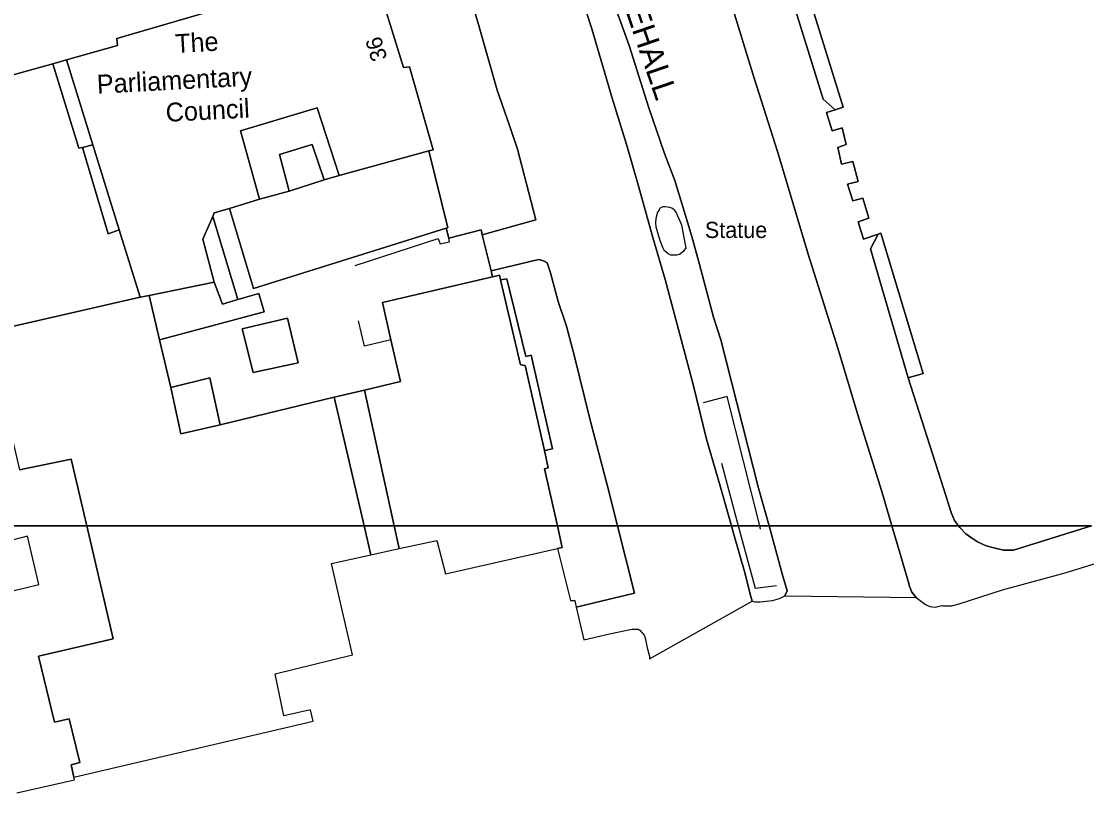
# Model space of a CAD drawing. Extents: x 529240 to 530363, y 179600 to 180767.
# Drawn here: x 530056.2 to 530155.2, y 180089.2 to 180160.9 of the extents above; entities that cross this region are included whole.
import ezdxf

# ---------------------------------------------------------------- set-up
doc = ezdxf.new("R2010")
doc.units = 0
for name, color, linetype in [('Building', 7, 'Continuous'), ('General surface', 7, 'Continuous'), ('Road Or Track', 7, 'Continuous'), ('Roadside', 7, 'Continuous'), ('Structure', 7, 'Continuous'), ('Unclassified', 7, 'Continuous')]:
    doc.layers.add(name, color=color, linetype=linetype)

msp = doc.modelspace()

# ---------------------------------------------------------------- linework, layer by layer
at = {"layer": 'Building'}
for points in [[(530054.35, 180155.6), (530059.15, 180156.95), (530060.4, 180157.3), (530065.15, 180158.65), (530065.1, 180159.3), (530088.7, 180166.2), (530081.7, 180190.2), (530080.2, 180189.85), (530076.55, 180188.95), (530075.7, 180192.2), (530074.7, 180196.1), (530074.35, 180197.35), (530059.6, 180193.8), (530053.95, 180192.45)], [(530088.7, 180166.2), (530065.1, 180159.3), (530065.15, 180158.65), (530060.4, 180157.3)], [(530131.85, 180152.65), (530132.6, 180152.9), (530128.55, 180166), (530127.05, 180165.55)], [(530128.55, 180166), (530132.6, 180152.9), (530131.85, 180152.65), (530131.05, 180152.4), (530131.6, 180150.7), (530132.5, 180151), (530132.9, 180149.45), (530132.1, 180149.15), (530132.45, 180147.6), (530133.5, 180147.85), (530134, 180146), (530133, 180145.75), (530133.5, 180144.2), (530134.45, 180144.45), (530135, 180142.6), (530134, 180142.25), (530134.5, 180140.65), (530135.85, 180141.1), (530136.1, 180141.2), (530140.05, 180128.15), (530138.65, 180127.75), (530141.95, 180117.5), (530142.65, 180115.25), (530142.95, 180114.5), (530143.335, 180114), (530155.69, 180114)], [(530094.1, 180148.85), (530094.5, 180148.95), (530092.3, 180156.65), (530091.75, 180156.6), (530090.1, 180161.9)], [(530060.4, 180157.3), (530059.15, 180156.95)], [(530060.4, 180157.3), (530062.85, 180149.4)], [(530059.15, 180156.95), (530054.35, 180155.6)], [(530078.35, 180144.35), (530076.6, 180150.7), (530083.7, 180152.85), (530085.75, 180146.55)], [(530135.85, 180141.1), (530134.5, 180140.65), (530134, 180142.25), (530135, 180142.6), (530134.45, 180144.45), (530133.5, 180144.2), (530133, 180145.75), (530134, 180146), (530133.5, 180147.85), (530132.45, 180147.6), (530132.1, 180149.15), (530132.9, 180149.45), (530132.5, 180151), (530131.6, 180150.7), (530131.05, 180152.4), (530131.85, 180152.65)], [(530061.9, 180149.15), (530062.85, 180149.4)], [(530062.85, 180149.4), (530065.3, 180141.5)], [(530081.1, 180145.1), (530080.2, 180148.5), (530083.25, 180149.45), (530084.35, 180146.15)], [(530061.9, 180149.15), (530064.3, 180141.15), (530065.3, 180141.5)], [(530085.75, 180146.55), (530094.1, 180148.85)], [(530095.7, 180141.65), (530095.85, 180141.7), (530094.1, 180148.85)], [(530085.75, 180146.55), (530084.35, 180146.15)], [(530084.35, 180146.15), (530081.1, 180145.1)], [(530081.1, 180145.1), (530078.35, 180144.35)], [(530074, 180142.75), (530074.15, 180143.1), (530075.55, 180143.5)], [(530075.55, 180143.5), (530078.35, 180144.35)], [(530075.55, 180143.5), (530077.8, 180136.05), (530095.7, 180141.65)], [(530074.15, 180136.65), (530073.1, 180140.65), (530074, 180142.75)], [(530065.3, 180141.5), (530067.25, 180135.25)], [(530138.65, 180127.75), (530140.05, 180128.15), (530136.1, 180141.2), (530135.85, 180141.1)], [(530068.1, 180135.4), (530074.15, 180136.65)], [(530076.35, 180135.05), (530074.9, 180134.6), (530074.15, 180136.65)], [(530100, 180137.15), (530089.8, 180134.75), (530090.55, 180131.3)], [(530100.75, 180136.85), (530100.65, 180137.3), (530100, 180137.15)], [(530104.85, 180121), (530103.05, 180128.9), (530102.6, 180128.95), (530100.75, 180136.85)], [(530069.05, 180131.3), (530078.8, 180133.9), (530078.3, 180135.6), (530076.35, 180135.05)], [(530067.25, 180135.25), (530053.05, 180132)], [(530067.25, 180135.25), (530068.1, 180135.4)], [(530069.05, 180131.3), (530068.1, 180135.4)], [(530053.05, 180132), (530056.05, 180119.2), (530060.85, 180120.2), (530062.298, 180114)], [(530070.1, 180126.85), (530069.05, 180131.3)], [(530090.55, 180131.3), (530091.45, 180127.4), (530088.1, 180126.6)], [(530070.1, 180126.85), (530073.75, 180127.75), (530074.7, 180123.4)], [(530143.335, 180114), (530142.95, 180114.5), (530142.65, 180115.25), (530141.95, 180117.5), (530138.65, 180127.75)], [(530074.7, 180123.4), (530071.05, 180122.55), (530070.1, 180126.85)], [(530088.1, 180126.6), (530085.3, 180125.95)], [(530088.1, 180126.6), (530090.886, 180114)], [(530085.3, 180125.95), (530074.7, 180123.4)], [(530088.073, 180114), (530085.3, 180125.95)], [(530106.048, 180114), (530104.85, 180119.3), (530105.2, 180119.4), (530104.85, 180121)], [(530062.298, 180114), (530064.75, 180103.5), (530057.8, 180101.9), (530059.3, 180095.75), (530060.65, 180096.05), (530061.65, 180092), (530060.85, 180091.8), (530061.1, 180090.65)], [(530088.7, 180111.3), (530088.073, 180114)], [(530090.886, 180114), (530091.35, 180111.9)], [(530106.05, 180111.9), (530106.5, 180112), (530106.048, 180114)], [(530155.69, 180114), (530148.45, 180111.75), (530147.5, 180111.75), (530146.6, 180111.95), (530145.9, 180112.15), (530145.1, 180112.5), (530144.45, 180112.95), (530144, 180113.25), (530143.45, 180113.85), (530143.335, 180114)]]:
    msp.add_lwpolyline(points, dxfattribs=at)
for points in [[(530067.25, 180135.25), (530068.1, 180135.4), (530074.15, 180136.65), (530073.1, 180140.65), (530074, 180142.75), (530074.15, 180143.1), (530075.55, 180143.5), (530078.35, 180144.35), (530076.6, 180150.7), (530083.7, 180152.85), (530085.75, 180146.55), (530094.1, 180148.85), (530094.5, 180148.95), (530092.3, 180156.65), (530091.75, 180156.6), (530090.1, 180161.9), (530088.7, 180166.2), (530065.1, 180159.3), (530065.15, 180158.65), (530060.4, 180157.3), (530062.85, 180149.4), (530065.3, 180141.5)], [(530065.3, 180141.5), (530062.85, 180149.4), (530061.9, 180149.15), (530064.3, 180141.15)], [(530081.1, 180145.1), (530084.35, 180146.15), (530083.25, 180149.45), (530080.2, 180148.5)], [(530085.75, 180146.55), (530084.35, 180146.15), (530081.1, 180145.1), (530078.35, 180144.35), (530075.55, 180143.5), (530077.8, 180136.05), (530095.7, 180141.65), (530095.85, 180141.7), (530094.1, 180148.85)], [(530074.15, 180136.65), (530068.1, 180135.4), (530069.05, 180131.3), (530078.8, 180133.9), (530078.3, 180135.6), (530076.35, 180135.05), (530074.9, 180134.6)], [(530090.886, 180114), (530106.048, 180114), (530104.85, 180119.3), (530105.2, 180119.4), (530104.85, 180121), (530103.05, 180128.9), (530102.6, 180128.95), (530100.75, 180136.85), (530100.65, 180137.3), (530100, 180137.15), (530089.8, 180134.75), (530090.55, 180131.3), (530091.45, 180127.4), (530088.1, 180126.6)], [(530062.298, 180114), (530088.073, 180114), (530085.3, 180125.95), (530074.7, 180123.4), (530071.05, 180122.55), (530070.1, 180126.85), (530069.05, 180131.3), (530068.1, 180135.4), (530067.25, 180135.25), (530053.05, 180132), (530056.05, 180119.2), (530060.85, 180120.2)], [(530076.75, 180132.3), (530077.75, 180128.25), (530081.95, 180129.15), (530080.95, 180133.3)], [(530074.7, 180123.4), (530073.75, 180127.75), (530070.1, 180126.85), (530071.05, 180122.55)], [(530088.073, 180114), (530090.886, 180114), (530088.1, 180126.6), (530085.3, 180125.95)], [(530062.298, 180114), (530064.75, 180103.5), (530057.8, 180101.9), (530059.3, 180095.75), (530060.65, 180096.05), (530061.65, 180092), (530060.85, 180091.8), (530061.1, 180090.65), (530083.35, 180095.85), (530083.1, 180096.9), (530080.6, 180096.35), (530079.8, 180100.25), (530087, 180102), (530085.8, 180107.25), (530085.05, 180110.5), (530088.7, 180111.3), (530088.073, 180114)], [(530088.073, 180114), (530088.7, 180111.3), (530091.35, 180111.9), (530090.886, 180114)], [(530090.886, 180114), (530091.35, 180111.9), (530094.85, 180112.65), (530095.65, 180109.55), (530106.05, 180111.9), (530106.5, 180112), (530106.048, 180114)], [(530143.335, 180114), (530143.45, 180113.85), (530144, 180113.25), (530144.45, 180112.95), (530145.1, 180112.5), (530145.9, 180112.15), (530146.6, 180111.95), (530147.5, 180111.75), (530148.45, 180111.75), (530155.69, 180114)]]:
    msp.add_lwpolyline(points, close=True, dxfattribs=at)
at = {"layer": 'General surface'}
for points in [[(530127.05, 180165.55), (530130.75, 180153.65), (530131.85, 180152.65), (530132.6, 180152.9), (530128.55, 180166)], [(530059.15, 180156.95), (530061.55, 180149.1), (530061.9, 180149.15), (530062.85, 180149.4), (530060.4, 180157.3)], [(530065.3, 180141.5), (530064.3, 180141.15), (530061.9, 180149.15), (530061.55, 180149.1), (530059.15, 180156.95), (530054.35, 180155.6), (530046.55, 180153.3), (530046.8, 180152.5), (530048.1, 180147.85), (530049.05, 180144.65), (530049.5, 180143.05), (530051.3, 180136.85), (530051.8, 180135.05), (530052.5, 180133.6), (530052.9, 180132.7), (530053.05, 180132), (530067.25, 180135.25)], [(530078.35, 180144.35), (530081.1, 180145.1), (530080.2, 180148.5), (530083.25, 180149.45), (530084.35, 180146.15), (530085.75, 180146.55), (530083.7, 180152.85), (530076.6, 180150.7)], [(530095.95, 180140.75), (530095.7, 180141.65), (530077.8, 180136.05), (530075.55, 180143.5), (530074.15, 180143.1), (530074, 180142.75), (530075.76, 180136.98), (530076.35, 180135.05), (530078.3, 180135.6), (530078.8, 180133.9), (530069.05, 180131.3), (530070.1, 180126.85), (530073.75, 180127.75), (530074.7, 180123.4), (530085.3, 180125.95), (530088.1, 180126.6), (530091.45, 180127.4), (530090.55, 180131.3), (530089.8, 180134.75), (530100, 180137.15), (530099.9, 180137.7), (530099.05, 180141.05), (530098.95, 180141.5)], [(530076.35, 180135.05), (530075.76, 180136.98), (530074, 180142.75), (530073.1, 180140.65), (530074.15, 180136.65), (530074.9, 180134.6)], [(530135.85, 180141.1), (530135.15, 180139.75), (530138.65, 180127.75), (530140.05, 180128.15), (530136.1, 180141.2)], [(530100.75, 180136.85), (530102.6, 180128.95), (530103.05, 180128.9), (530104.85, 180121), (530105.6, 180121.15), (530103.6, 180129.85), (530103.1, 180129.75), (530101.35, 180136.95)], [(530076.75, 180132.3), (530080.95, 180133.3), (530081.95, 180129.15), (530077.75, 180128.25)], [(530052.2, 180107.2), (530057.85, 180108.55), (530056.8, 180113.05), (530051.1, 180111.55)]]:
    msp.add_lwpolyline(points, close=True, dxfattribs=at)
for points in [[(529931.174, 180114), (530062.298, 180114), (530060.85, 180120.2), (530056.05, 180119.2)], [(530055.8, 180089.2), (530061.15, 180090.4), (530061.1, 180090.65), (530060.85, 180091.8), (530061.65, 180092), (530060.65, 180096.05), (530059.3, 180095.75), (530057.8, 180101.9), (530064.75, 180103.5), (530062.298, 180114), (529931.174, 180114)]]:
    msp.add_lwpolyline(points, dxfattribs=at)
at = {"layer": 'Road Or Track'}
for points in [[(530137.131, 180114), (530136.2, 180117.2), (530134.1, 180123.9), (530132.1, 180130.5), (530129.35, 180139.25), (530126.55, 180148.7), (530124.35, 180155.6), (530122, 180163.2), (530119.65, 180171.3), (530116.8, 180180.2), (530116.45, 180181.45), (530116.4, 180182.05), (530116.45, 180182.6), (530116.65, 180183.1)], [(530103.4, 180179.55), (530103.6, 180178.95), (530104.85, 180174.65), (530105.7, 180171.3), (530107.55, 180165.45), (530109.25, 180160.2), (530111.15, 180153.75), (530112.5, 180149.35), (530113.55, 180145.7), (530114.9, 180140.8), (530116.05, 180136.9), (530117.3, 180132.25), (530118.65, 180127.15), (530119.9, 180122.05), (530121.15, 180117.8), (530122.224, 180114)], [(530125.719, 180114), (530124.75, 180117.5), (530121.25, 180131.3), (530120.55, 180133.4), (530119.25, 180138.3), (530118.55, 180140.9), (530117.75, 180143.55), (530116.95, 180146.1), (530116, 180148.6), (530114.55, 180152.85), (530112.7, 180158.65), (530110.5, 180164.75), (530107.95, 180172.25), (530105.75, 180178.55), (530105.35, 180179.76)], [(530099.05, 180141.05), (530104.05, 180142.45), (530102.35, 180149), (530101.6, 180151.2), (530100.45, 180154.5), (530098.65, 180160.8), (530096.8, 180166.95), (530095.95, 180169.75), (530094.65, 180174.5), (530093.83, 180177.2)], [(530096.8, 180166.95), (530098.65, 180160.8), (530100.45, 180154.5), (530101.6, 180151.2), (530102.35, 180149), (530104.05, 180142.45), (530099.05, 180141.05), (530099.9, 180137.7), (530104.05, 180138.7), (530104.35, 180138.75), (530104.55, 180138.7), (530104.8, 180138.6), (530105.1, 180138.45), (530105.4, 180137.5), (530106.1, 180134.85), (530106.9, 180132.55), (530107.6, 180129.85), (530109.05, 180123.95), (530110.7, 180117.7), (530111.63, 180114), (530122.224, 180114), (530121.15, 180117.8), (530119.9, 180122.05), (530118.65, 180127.15), (530117.3, 180132.25), (530116.05, 180136.9), (530114.9, 180140.8), (530113.55, 180145.7), (530112.5, 180149.35), (530111.15, 180153.75), (530109.25, 180160.2), (530107.55, 180165.45)], [(530110.5, 180164.75), (530112.7, 180158.65), (530114.55, 180152.85), (530116, 180148.6), (530116.95, 180146.1), (530117.75, 180143.55), (530118.55, 180140.9), (530119.25, 180138.3), (530120.55, 180133.4), (530121.25, 180131.3), (530124.75, 180117.5), (530125.719, 180114), (530137.131, 180114), (530136.2, 180117.2), (530134.1, 180123.9), (530132.1, 180130.5), (530129.35, 180139.25), (530126.55, 180148.7), (530124.35, 180155.6), (530122, 180163.2)], [(530111.63, 180114), (530110.7, 180117.7), (530109.05, 180123.95), (530107.6, 180129.85), (530106.9, 180132.55), (530106.1, 180134.85), (530105.4, 180137.5), (530105.1, 180138.45), (530104.8, 180138.6), (530104.55, 180138.7), (530104.35, 180138.75), (530104.05, 180138.7), (530099.9, 180137.7)], [(530107.8, 180106.45), (530113.2, 180107.75), (530111.63, 180114)], [(530122.224, 180114), (530122.45, 180113.2), (530123.5, 180109.55), (530123.95, 180107.65), (530124.15, 180107)], [(530127.2, 180107.5), (530127.4, 180107.95), (530126.95, 180109.55), (530125.719, 180114)], [(530139.4, 180107.35), (530139, 180107.85), (530138.75, 180108.45), (530138.7, 180108.65), (530137.8, 180111.7), (530137.131, 180114)]]:
    msp.add_lwpolyline(points, dxfattribs=at)
for points in [[(530111.63, 180114), (530113.2, 180107.75), (530107.8, 180106.45), (530108.5, 180103.4), (530110.9, 180103.95), (530112.95, 180104.4), (530113.55, 180104.4), (530113.7, 180104.3), (530113.9, 180104.1), (530114.1, 180103.85), (530114.2, 180103.6), (530114.4, 180102.65), (530114.6, 180101.9), (530114.6, 180101.65), (530124.15, 180107), (530123.95, 180107.65), (530123.5, 180109.55), (530122.45, 180113.2), (530122.224, 180114)], [(530125.719, 180114), (530126.95, 180109.55), (530127.4, 180107.95), (530127.2, 180107.5), (530139.4, 180107.35), (530139, 180107.85), (530138.75, 180108.45), (530138.7, 180108.65), (530137.8, 180111.7), (530137.131, 180114)]]:
    msp.add_lwpolyline(points, close=True, dxfattribs=at)
at = {"layer": 'Roadside'}
for points in [[(530090.1, 180161.9), (530091.75, 180156.6), (530092.3, 180156.65), (530094.5, 180148.95), (530094.1, 180148.85), (530095.85, 180141.7), (530095.7, 180141.65), (530095.95, 180140.75), (530098.95, 180141.5), (530099.05, 180141.05), (530104.05, 180142.45), (530102.35, 180149), (530101.6, 180151.2), (530100.45, 180154.5), (530098.65, 180160.8), (530096.8, 180166.95)], [(530107.55, 180165.45), (530109.25, 180160.2), (530111.15, 180153.75), (530112.5, 180149.35), (530113.55, 180145.7), (530114.9, 180140.8), (530116.05, 180136.9), (530117.3, 180132.25), (530118.65, 180127.15), (530119.9, 180122.05), (530121.15, 180117.8), (530122.224, 180114), (530125.719, 180114), (530124.75, 180117.5), (530121.25, 180131.3), (530120.55, 180133.4), (530119.25, 180138.3), (530118.55, 180140.9), (530117.75, 180143.55), (530116.95, 180146.1), (530116, 180148.6), (530114.55, 180152.85), (530112.7, 180158.65), (530110.5, 180164.75)], [(530122, 180163.2), (530124.35, 180155.6), (530126.55, 180148.7), (530129.35, 180139.25), (530132.1, 180130.5), (530134.1, 180123.9), (530136.2, 180117.2), (530137.131, 180114), (530143.335, 180114), (530142.95, 180114.5), (530142.65, 180115.25), (530141.95, 180117.5), (530138.65, 180127.75), (530135.15, 180139.75), (530135.85, 180141.1), (530134.5, 180140.65), (530134, 180142.25), (530135, 180142.6), (530134.45, 180144.45), (530133.5, 180144.2), (530133, 180145.75), (530134, 180146), (530133.5, 180147.85), (530132.45, 180147.6), (530132.1, 180149.15), (530132.9, 180149.45), (530132.5, 180151), (530131.6, 180150.7), (530131.05, 180152.4), (530131.85, 180152.65), (530130.75, 180153.65), (530127.05, 180165.55)], [(530155.69, 180114), (530148.45, 180111.75), (530147.5, 180111.75), (530146.6, 180111.95), (530145.9, 180112.15), (530145.1, 180112.5), (530144.45, 180112.95), (530144, 180113.25), (530143.45, 180113.85), (530143.335, 180114), (530137.131, 180114), (530137.8, 180111.7), (530138.7, 180108.65), (530138.75, 180108.45), (530139, 180107.85), (530139.4, 180107.35), (530140.25, 180106.7), (530140.65, 180106.5), (530141.15, 180106.45), (530141.65, 180106.55), (530141.77, 180106.6), (530141.86, 180106.58), (530141.99, 180106.55), (530142.69, 180106.58), (530143.38, 180106.75), (530147.43, 180108.04), (530153.24, 180109.63), (530154.54, 180110.04), (530155.94, 180110.48)]]:
    msp.add_lwpolyline(points, dxfattribs=at)
for points in [[(530115.5, 180143.35), (530115.35, 180143.15), (530115.2, 180142.55), (530115.15, 180142.15), (530115.2, 180141.8), (530115.4, 180141.05), (530115.6, 180140.45), (530115.8, 180139.9), (530115.95, 180139.65), (530116.15, 180139.45), (530116.35, 180139.3), (530116.55, 180139.2), (530117.15, 180139.2), (530117.4, 180139.25), (530117.8, 180139.55), (530118, 180139.8), (530117.85, 180140.65), (530117.6, 180141.95), (530117.4, 180142.45), (530117.2, 180142.85), (530117.1, 180143.1), (530116.95, 180143.3), (530116.75, 180143.5), (530116.5, 180143.6), (530116.05, 180143.65), (530115.85, 180143.65), (530115.55, 180143.5)], [(530106.048, 180114), (530111.63, 180114), (530110.7, 180117.7), (530109.05, 180123.95), (530107.6, 180129.85), (530106.9, 180132.55), (530106.1, 180134.85), (530105.4, 180137.5), (530105.1, 180138.45), (530104.8, 180138.6), (530104.55, 180138.7), (530104.35, 180138.75), (530104.05, 180138.7), (530099.9, 180137.7), (530100, 180137.15), (530100.65, 180137.3), (530100.75, 180136.85), (530101.35, 180136.95), (530103.1, 180129.75), (530103.6, 180129.85), (530105.6, 180121.15), (530104.85, 180121), (530105.2, 180119.4), (530104.85, 180119.3)], [(530106.048, 180114), (530106.5, 180112), (530106.05, 180111.9), (530107.25, 180107.05), (530107.65, 180107.05), (530107.8, 180106.45), (530113.2, 180107.75), (530111.63, 180114)], [(530122.224, 180114), (530122.45, 180113.2), (530123.5, 180109.55), (530123.95, 180107.65), (530124.15, 180107), (530124.4, 180106.95), (530124.9, 180106.95), (530125.45, 180107), (530126.05, 180107.05), (530126.7, 180107.25), (530127.2, 180107.5), (530127.4, 180107.95), (530126.95, 180109.55), (530125.719, 180114)]]:
    msp.add_lwpolyline(points, close=True, dxfattribs=at)
at = {"layer": 'Structure'}
msp.add_lwpolyline([(530115.55, 180143.5), (530115.5, 180143.35), (530115.35, 180143.15), (530115.2, 180142.55), (530115.15, 180142.15), (530115.2, 180141.8), (530115.4, 180141.05), (530115.6, 180140.45), (530115.8, 180139.9), (530115.95, 180139.65), (530116.15, 180139.45), (530116.35, 180139.3), (530116.55, 180139.2), (530117.15, 180139.2), (530117.4, 180139.25), (530117.8, 180139.55), (530118, 180139.8), (530117.85, 180140.65), (530117.6, 180141.95), (530117.4, 180142.45), (530117.2, 180142.85), (530117.1, 180143.1), (530116.95, 180143.3), (530116.75, 180143.5), (530116.5, 180143.6), (530116.05, 180143.65), (530115.85, 180143.65)], close=True, dxfattribs=at)
at = {"layer": 'Unclassified'}
for points in [[(530127.05, 180165.55), (530130.75, 180153.65), (530131.85, 180152.65)], [(530059.15, 180156.95), (530061.55, 180149.1), (530061.9, 180149.15)], [(530115.55, 180143.5), (530115.5, 180143.35), (530115.35, 180143.15), (530115.2, 180142.55), (530115.15, 180142.15), (530115.2, 180141.8), (530115.4, 180141.05), (530115.6, 180140.45), (530115.8, 180139.9), (530115.95, 180139.65), (530116.15, 180139.45), (530116.35, 180139.3), (530116.55, 180139.2), (530117.15, 180139.2), (530117.4, 180139.25), (530117.8, 180139.55), (530118, 180139.8), (530117.85, 180140.65), (530117.6, 180141.95), (530117.4, 180142.45), (530117.2, 180142.85), (530117.1, 180143.1), (530116.95, 180143.3), (530116.75, 180143.5), (530116.5, 180143.6), (530116.05, 180143.65), (530115.85, 180143.65), (530115.55, 180143.5)], [(530076.35, 180135.05), (530075.76, 180136.98), (530074, 180142.75)], [(530095.95, 180140.75), (530095.7, 180141.65)], [(530099.05, 180141.05), (530098.95, 180141.5), (530095.95, 180140.75)], [(530087.25, 180138.2), (530094.95, 180140.7), (530095.15, 180140.2), (530096, 180140.4), (530095.95, 180140.75)], [(530099.9, 180137.7), (530099.05, 180141.05)], [(530135.85, 180141.1), (530135.15, 180139.75), (530138.65, 180127.75)], [(530100, 180137.15), (530099.9, 180137.7)], [(530104.85, 180121), (530105.6, 180121.15), (530103.6, 180129.85), (530103.1, 180129.75), (530101.35, 180136.95), (530100.75, 180136.85)], [(530076.75, 180132.3), (530080.95, 180133.3), (530081.95, 180129.15), (530077.75, 180128.25), (530076.75, 180132.3)], [(530090.55, 180131.3), (530088.1, 180130.7), (530087.55, 180133.05)], [(530124.855, 180114), (530121.83, 180126.02), (530119.59, 180125.43)], [(530121.29, 180119.81), (530122.863, 180114)], [(530122.863, 180114), (530124.43, 180108.21), (530126.41, 180108.47)], [(530124.93, 180113.7), (530124.855, 180114)]]:
    msp.add_lwpolyline(points, dxfattribs=at)

# ---------------------------------------------------------------- texts
at = {"layer": 'Road Or Track'}
msp.add_text('WHITEHALL', height=2.125, rotation=288.8, dxfattribs=at).set_placement((530110, 180168.8))
at = {"layer": 'Structure'}
msp.add_text('Statue', height=1.5, dxfattribs=at).set_placement((530119.75, 180140.75))
at = {"layer": 'Unclassified'}
for s, height, rotation, p in [('The', 1.75, 3.4, (530070.56, 180157.93)), ('36', 1.5, 107, (530090.25, 180157.45)), ('Parliamentary', 1.75, 3, (530063.28, 180154.16)), ('Council', 1.75, 3, (530069.68, 180151.54))]:
    msp.add_text(s, height=height, rotation=rotation, dxfattribs=at).set_placement(p)

doc.saveas('drawing.dxf')
